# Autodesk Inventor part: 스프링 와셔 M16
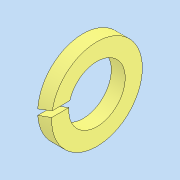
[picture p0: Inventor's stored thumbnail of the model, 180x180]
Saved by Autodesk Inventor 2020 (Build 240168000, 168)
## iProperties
Created: 2025-01
Part Number: 스프링 와셔 M16
Material: 강철, 연강
Description: 스프링 잠금 와셔
Document SubType Name: Modeling
Designer: 1강의실14
Density: 7.85 g/cm^3
Appearance: 기본값
Author: jhkim
Sending System: Autodesk Inventor 2025
Preprocessor: ST-DEVELOPER v20
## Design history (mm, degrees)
feature "Solid1"
node "솔리드1"
